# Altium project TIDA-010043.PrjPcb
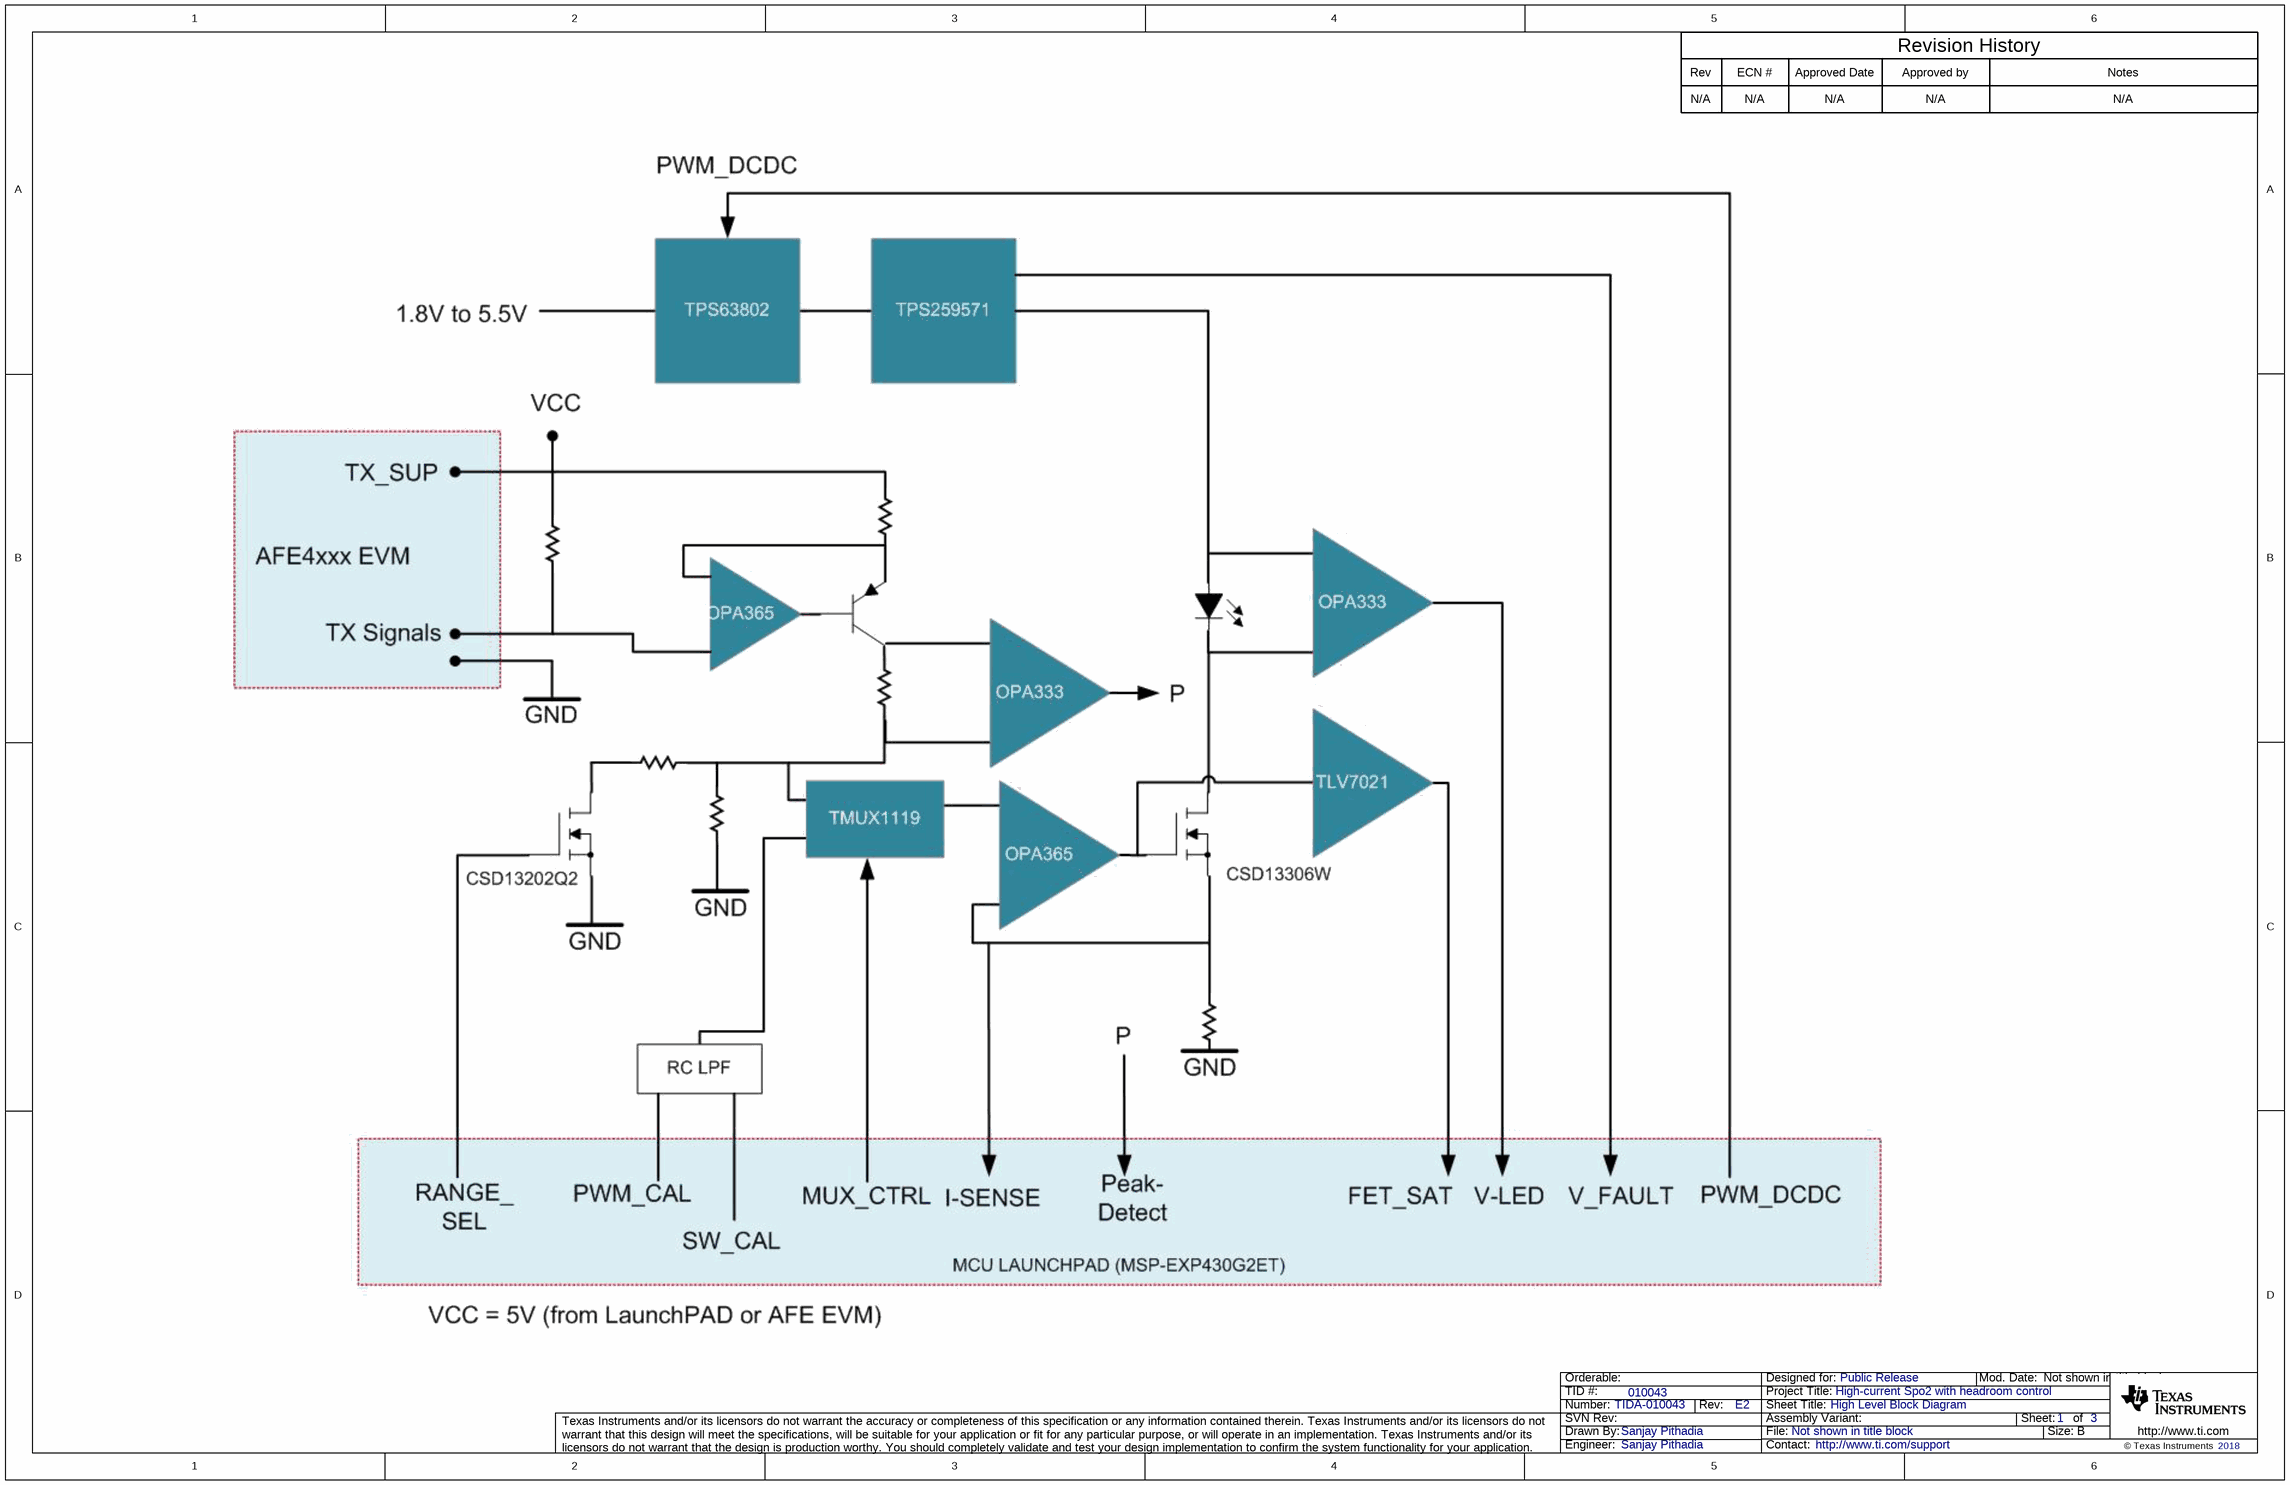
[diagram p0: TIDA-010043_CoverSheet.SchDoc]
CopyrightYear: 2018; PCB_Layout: TESSOLVE; PCB_Rev: E2; PRJ_Customer: Public Release; PRJ_Engineer: Sanjay Pithadia; PRJ_Number: TIDA-010043; PRJ_Title: High-current Spo2 with headroom control; SCH_Rev: E2; TechSupport: http://www.ti.com/support; TID: 010043
3 sheets, 122 parts. Net scope: global (net labels, ports and power ports of the same name join across sheets).
Board file: TIDA-010043_PCB.PcbDoc
Sheets:
  TIDA-010043_CoverSheet.SchDoc
  TIDA-010043_Main.SchDoc
  TIDA-010043_EVM_Hardware.SchDoc

## Sheet TIDA-010043_CoverSheet.SchDoc: High Level Block Diagram
size 431 x 279 mm; Date: Not shown in title block; ApprovedBy: Not shown in title block; CheckedBy: Not shown in title block; Author: Not shown in title block; CompanyName: Not shown in title block; DrawnBy: Sanjay Pithadia; Engineer: Sanjay Pithadia; Organization: Not shown in title block; Address1: Not shown in title block; Address2: Not shown in title block; Address3: Not shown in title block; Address4: Not shown in title block; DocumentNumber: 1; Revision: Use project parameter SCH_Rev; SheetNumber: 1; SheetTotal: 3; PageSetup: Record=PageOptions¦CenterHorizontal=True¦CenterVertical=True¦PrintScale=1.00¦XCorrection=1.00¦YCorrection=1.00¦PrintKind=0¦BorderSize=5000000¦LeftOffset=0¦BottomOffset=0¦Orientation=2¦PaperLength=1000¦PaperWidth=1000¦Scale=100¦PaperSource=15¦PrintQuality=600¦MediaType=1¦DitherType=10¦PaperKind=Letter¦PrintScaleMode=1

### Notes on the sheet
- Rev
- N/A
- ECN #
- Approved Date
- Approved by
- Revision History
- Notes

## Sheet TIDA-010043_Main.SchDoc: Main
size 431 x 279 mm; Date: Not shown in title block; ApprovedBy: Not shown in title block; CheckedBy: Not shown in title block; Author: Not shown in title block; CompanyName: Not shown in title block; DrawnBy: Sanjay Pithadia; Engineer: Sanjay Pithadia; Organization: Not shown in title block; Address1: Not shown in title block; Address2: Not shown in title block; Address3: Not shown in title block; Address4: Not shown in title block; DocumentNumber: 1; Revision: Use project parameter SCH_Rev; SheetNumber: 2; SheetTotal: 3; PageSetup: Record=PageOptions¦CenterHorizontal=True¦CenterVertical=True¦PrintScale=1.00¦XCorrection=1.00¦YCorrection=1.00¦PrintKind=0¦BorderSize=5000000¦LeftOffset=0¦BottomOffset=0¦Orientation=2¦PaperLength=1000¦PaperWidth=1000¦Scale=100¦PaperSource=15¦PrintQuality=600¦MediaType=1¦DitherType=10¦PaperKind=Letter¦PrintScaleMode=1
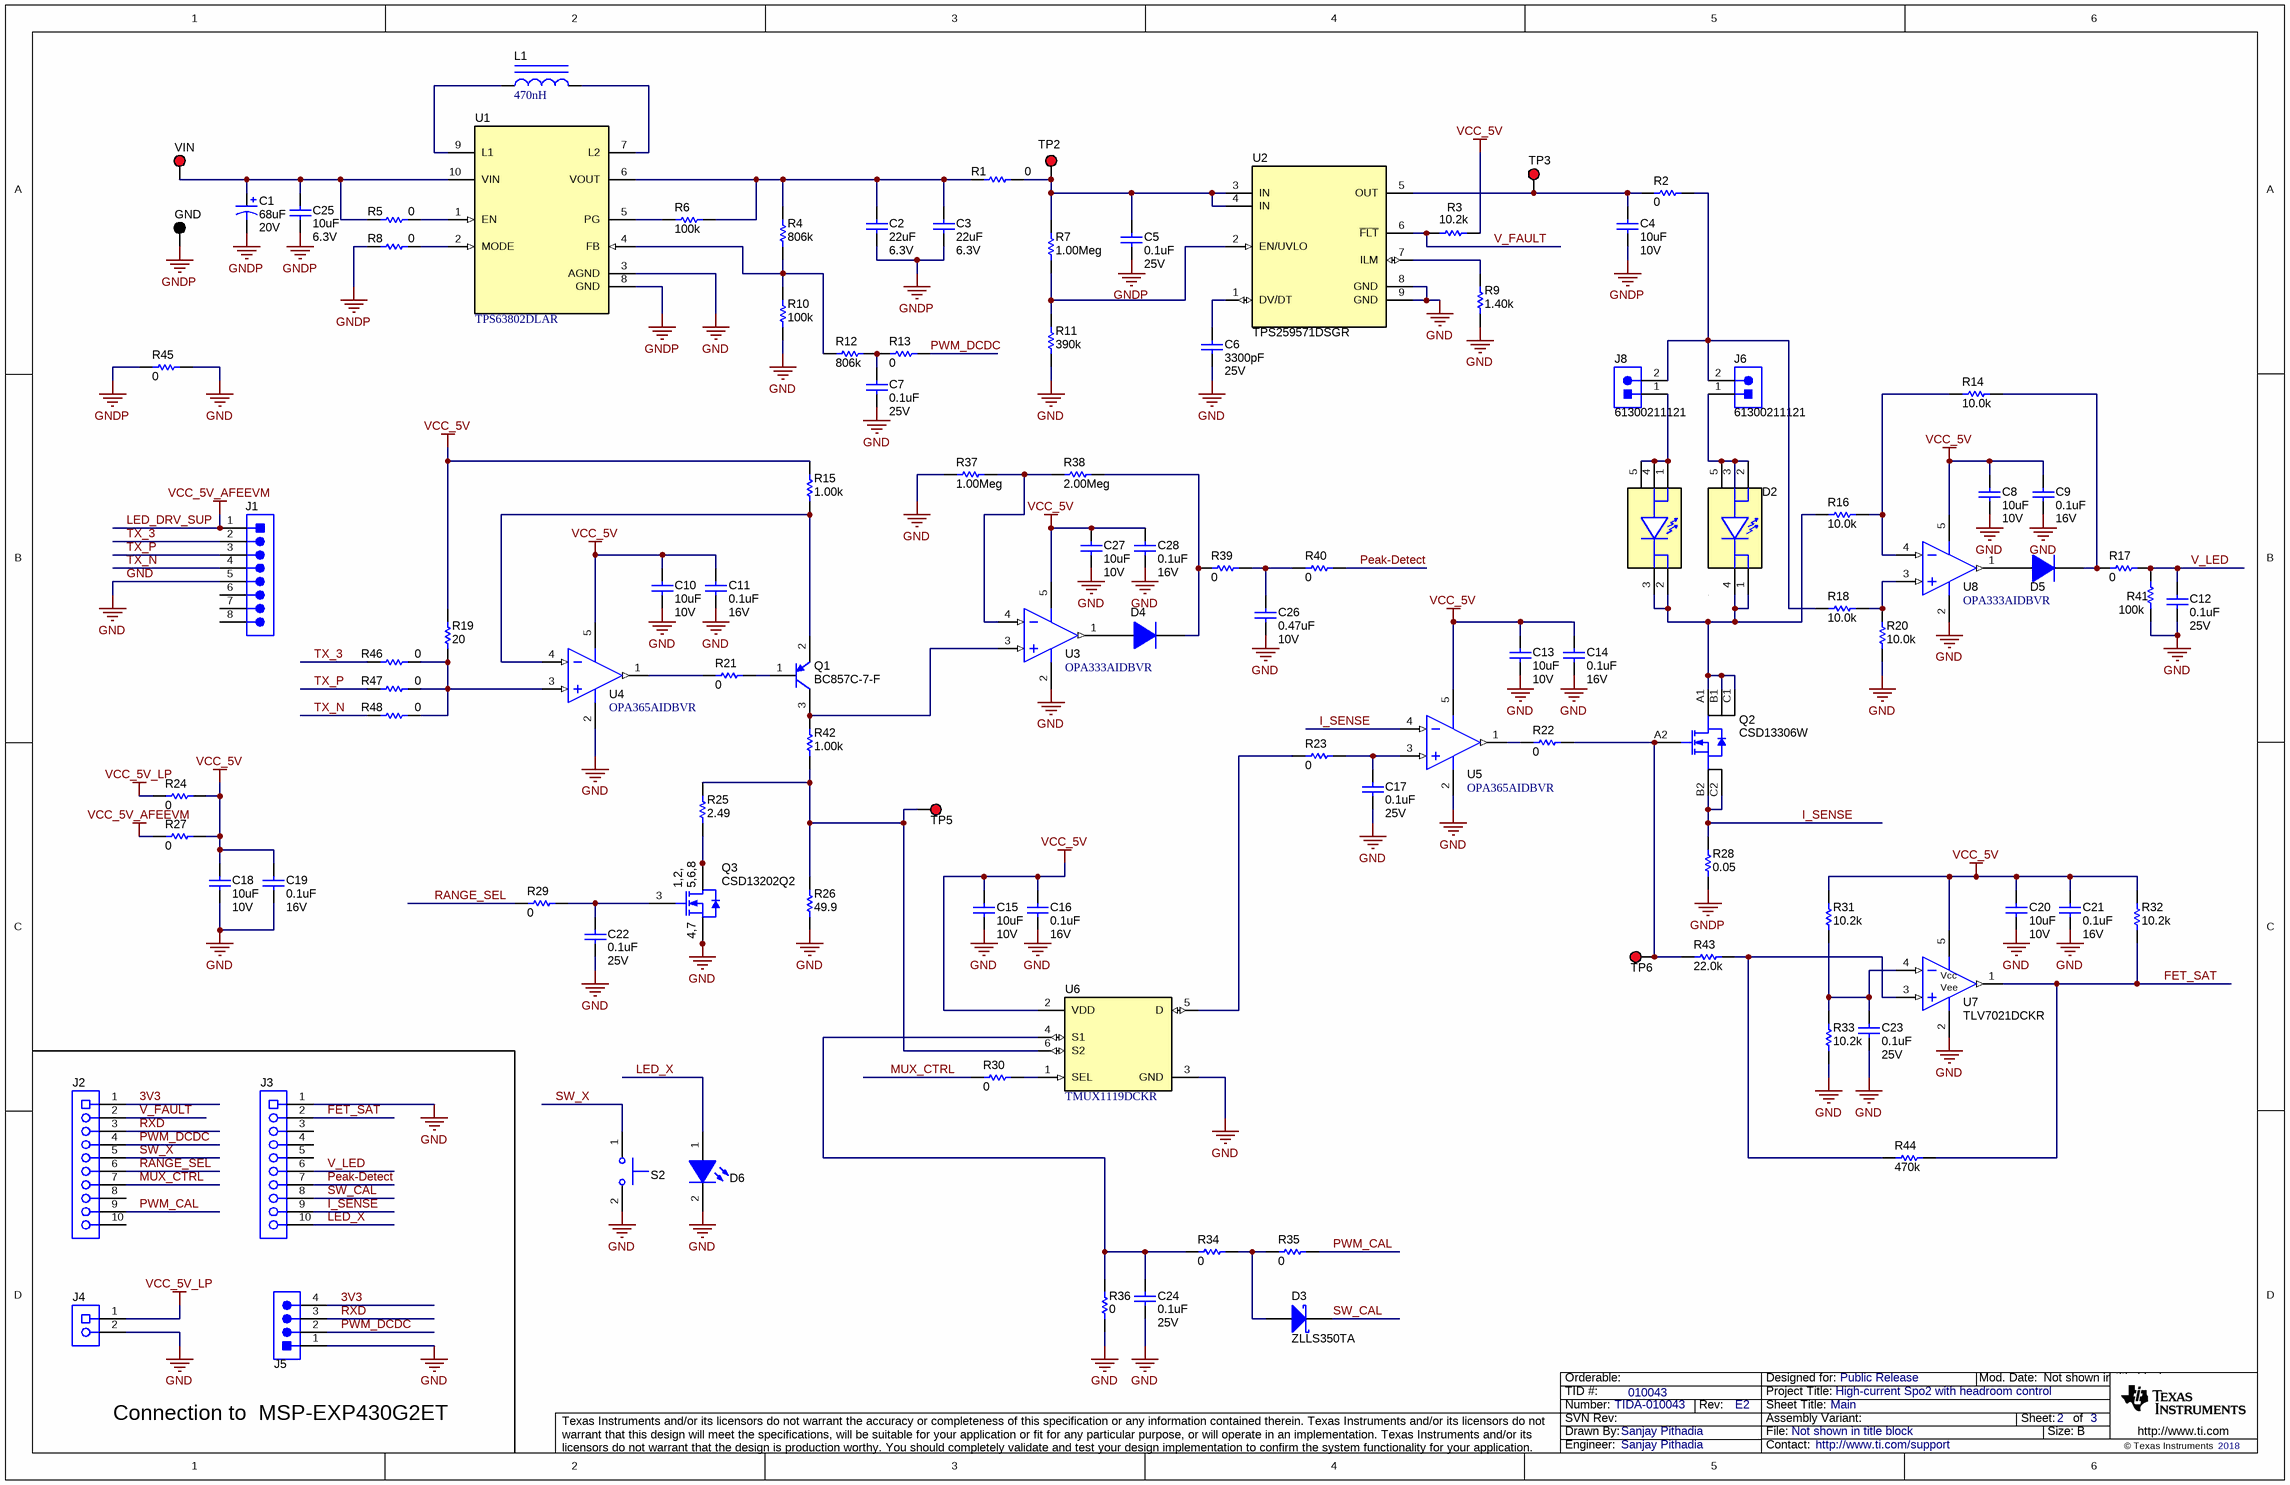
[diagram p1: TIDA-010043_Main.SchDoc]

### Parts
C1  value 68uF  Value2: 20V  [7343-31]  (hidden comment: T495D686K020ATE150)
C2  value 22uF  Value2: 6.3V  [0603]  (hidden comment: GRM188R60J226MEA0D)
C3  value 22uF  Value2: 6.3V  [0603]  (hidden comment: GRM188R60J226MEA0D)
C4  value 10uF  Value2: 10V  [0603]  (hidden comment: GRM188Z71A106MA73D)
C5  value 0.1uF  Value2: 25V  [0603]  (hidden comment: 06033C104KAT2A)
C6  value 3300pF  Value2: 25V  [0603]  (hidden comment: GRM188R71E332KA01D)
C7  value 0.1uF  Value2: 25V  [0603]  (hidden comment: 06033C104KAT2A)
C8  value 10uF  Value2: 10V  [0805_HV]  (hidden comment: 885012207026)
C9  value 0.1uF  Value2: 16V  [0402]  (hidden comment: 885012205037)
C10  value 10uF  Value2: 10V  [0805_HV]  (hidden comment: 885012207026)
C11  value 0.1uF  Value2: 16V  [0402]  (hidden comment: 885012205037)
C12  value 0.1uF  Value2: 25V  [0603]  (hidden comment: 06033C104KAT2A)
C13  value 10uF  Value2: 10V  [0805_HV]  (hidden comment: 885012207026)
C14  value 0.1uF  Value2: 16V  [0402]  (hidden comment: 885012205037)
C15  value 10uF  Value2: 10V  [0805_HV]  (hidden comment: 885012207026)
C16  value 0.1uF  Value2: 16V  [0402]  (hidden comment: 885012205037)
C17  value 0.1uF  Value2: 25V  [0603]  (hidden comment: 06033C104KAT2A)
C18  value 10uF  Value2: 10V  [0805_HV]  (hidden comment: 885012207026)
C19  value 0.1uF  Value2: 16V  [0402]  (hidden comment: 885012205037)
C20  value 10uF  Value2: 10V  [0805_HV]  (hidden comment: 885012207026)
C21  value 0.1uF  Value2: 16V  [0402]  (hidden comment: 885012205037)
C22  value 0.1uF  Value2: 25V  [0603]  (hidden comment: 06033C104KAT2A)
C23  value 0.1uF  Value2: 25V  [0603]  (hidden comment: 06033C104KAT2A)
C24  value 0.1uF  Value2: 25V  [0603]  (hidden comment: 06033C104KAT2A)
C25  value 10uF  Value2: 6.3V  [0603]  (hidden comment: GRM188R60J106ME84)
C26  value 0.47uF  Value2: 10V  [0603]  (hidden comment: GRM188R71A474KA61D)
C27  value 10uF  Value2: 10V  [0805_HV]  (hidden comment: 885012207026)
C28  value 0.1uF  Value2: 16V  [0402]  (hidden comment: 885012205037)
D1  LZ1-00G102-0000  [LED_LZ1_Green]  (value not drawn)
D2  LZ1-00R102-0000  [LED_LZ1_Red]  (value not drawn)
D3  ZLLS350TA  [SOD-523]
D4  1N4148W-7-F  [SOD-123]  (value not drawn)
D5  1N4148W-7-F  [SOD-123]  (value not drawn)
D6  SM0603GCL  [SM0603GCL_GREEN]  (value not drawn)
GND  5001  [Keystone5001]  (value not drawn)
J1  850-10-008-20-001000  [Mill-Max_850-10-008-20-001000]  (value not drawn)
J2  61301011821  [Wurth_61301011821]  (value not drawn)
J3  61301011821  [Wurth_61301011821]  (value not drawn)
J4  PPTC021LFBN-RC  [CONN_PPTC021LFBN-RC]  (value not drawn)
J5  61000418221  [Wurth_61000418221]  (value not drawn)
J6  61300211121  [WURTH_61300211121]
J8  61300211121  [WURTH_61300211121]
L1  ValueDisplayed: 470nH  [DFE201612E]  (hidden comment: DFE201612E-R47M=P2)
Q1  BC857C-7-F  [SOT-23]
Q2  CSD13306W  [YZC0006ABAB]
Q3  CSD13202Q2  [DQK0006C]
R1  value 0  [5106]  (hidden comment: 5106)
R2  value 0  [5106]  (hidden comment: 5106)
R3  value 10.2k  [0603]  (hidden comment: RC0603FR-0710K2L)
R4  value 806k  [0603]  (hidden comment: RC0603FR-07806KL)
R5  value 0  [0603]  (hidden comment: RMCF0603ZT0R00)
R6  value 100k  [0603]  (hidden comment: CRCW0603100KFKEA)
R7  value 1.00Meg  [0603]  (hidden comment: RC0603FR-071ML)
R8  value 0  [0603]  (hidden comment: RMCF0603ZT0R00)
R9  value 1.40k  [0603]  (hidden comment: RC0603FR-071K4L)
R10  value 100k  [0603]  (hidden comment: CRCW0603100KFKEA)
R11  value 390k  [0603]  (hidden comment: RC0603FR-07390KL)
R12  value 806k  [0603]  (hidden comment: RC0603FR-07806KL)
R13  value 0  [0603]  (hidden comment: RMCF0603ZT0R00)
R14  value 10.0k  [0603]  (hidden comment: RMCF0603FT10K0)
R15  value 1.00k  [0603]  (hidden comment: ERJ-3EKF1001V)
R16  value 10.0k  [0603]  (hidden comment: RMCF0603FT10K0)
R17  value 0  [0603]  (hidden comment: RMCF0603ZT0R00)
R18  value 10.0k  [0603]  (hidden comment: RMCF0603FT10K0)
R19  Res_ohm: 20  [1206]  (hidden comment: CRCW120620R0FKEAHP)
R20  value 10.0k  [0603]  (hidden comment: RMCF0603FT10K0)
R21  value 0  [0603]  (hidden comment: RMCF0603ZT0R00)
R22  value 0  [0603]  (hidden comment: RMCF0603ZT0R00)
R23  value 0  [0603]  (hidden comment: RMCF0603ZT0R00)
R24  value 0  [0603]  (hidden comment: RMCF0603ZT0R00)
R25  value 2.49  [0603]  (hidden comment: CRCW06032R49FKEA)
R26  value 49.9  [0603]  (hidden comment: CRCW060349R9FKEA)
R27  value 0  [0603]  (hidden comment: RMCF0603ZT0R00)
R28  value 0.05  [1206]  (hidden comment: CRM1206-FZ-R050ELF)
R29  value 0  [0603]  (hidden comment: RMCF0603ZT0R00)
R30  value 0  [0603]  (hidden comment: RMCF0603ZT0R00)
R31  value 10.2k  [0603]  (hidden comment: RC0603FR-0710K2L)
R32  value 10.2k  [0603]  (hidden comment: RC0603FR-0710K2L)
R33  value 10.2k  [0603]  (hidden comment: RC0603FR-0710K2L)
R34  value 0  [0603]  (hidden comment: RMCF0603ZT0R00)
R35  value 0  [0603]  (hidden comment: RMCF0603ZT0R00)
R36  value 0  [0603]  (hidden comment: RMCF0603ZT0R00)
R37  value 1.00Meg  [0603]  (hidden comment: RC0603FR-071ML)
R38  value 2.00Meg  [0603]  (hidden comment: RC0603FR-072ML)
R39  value 0  [0603]  (hidden comment: RMCF0603ZT0R00)
R40  value 0  [0603]  (hidden comment: RMCF0603ZT0R00)
R41  value 100k  [0603]  (hidden comment: RC0603FR-07100KL)
R42  value 1.00k  [0603]  (hidden comment: ERJ-3EKF1001V)
R43  value 22.0k  [0603]  (hidden comment: ERJ-3EKF2202V)
R44  value 470k  [0603]  (hidden comment: RC0603FR-07470KL)
R45  value 0  [0603]  (hidden comment: RMCF0603ZT0R00)
R46  value 0  [0603]  (hidden comment: RMCF0603ZT0R00)
R47  value 0  [0603]  (hidden comment: RMCF0603ZT0R00)
R48  value 0  [0603]  (hidden comment: RMCF0603ZT0R00)
S2  SKRKAEE010  [SW_SKRKAEE010]  (value not drawn)
TP2  5000  [Keystone5000]  (value not drawn)
TP3  5000  [Keystone5000]  (value not drawn)
TP5  5000  [Keystone5000]  (value not drawn)
TP6  5000  [Keystone5000]  (value not drawn)
U1  TPS63802DLAR  [DLA0010A]
U2  TPS259571DSGR  [DSG0008A]
U3  OPA333AIDBVR  [DBV0005A_N]
U4  OPA365AIDBVR  [DBV0005A_N]
U5  OPA365AIDBVR  [DBV0005A_N]
U6  TMUX1119DCKR  [DCK0006A_N]  (no BOM)
U7  TLV7021DCKR  [DCK0005A_L]
U8  OPA333AIDBVR  [DBV0005A_N]
VIN  5000  [Keystone5000]  (value not drawn)

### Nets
GND: C6.2 C7.2 C8.2 C9.2 C10.2 C11.2 C12.2 C13.2 C14.2 C15.2 C16.2 C17.2 C18.2 C19.2 C20.2 C21.2 C22.2 C23.2 C24.2 C26.2 C27.2 C28.2 D6.2(K) J1.5 J3.1 J4.2 J5.1 Q3.4(S) Q3.7(S) R9.1 R10.2 R11.1 R20.1 R26.1 R33.1 R36.1 R37.1 R41.1 R45.2 S2.2 U1.3(AGND) U2.8(GND) U2.9(GND) U3.2(V-) U4.2(V-) U5.2(V-) U6.3(GND) U7.2(VEE) U8.2(V-)
GNDP: C1.2(-) C2.2 C3.2 C4.2 C5.2 C25.2 GND.1 R8.1 R28.1 R45.1 U1.8(GND)
LED_DRV_SUP: J1.1 R27.1  [also labelled VCC_5V_AFEEVM]
VCC_5V: C8.1 C9.1 C10.1 C11.1 C13.1 C14.1 C15.1 C16.1 C18.1 C19.1 C20.1 C21.1 C27.1 C28.1 R3.2 R15.2 R19.2 R24.2 R27.2 R31.2 R32.2 U3.5(V+) U4.5(V+) U5.5(V+) U6.2(VDD) U7.5(VCC) U8.5(V+)
VCC_5V_LP: J4.1 R24.1
3V3: J2.1 J5.4
FET_SAT: J3.2 R32.1 R44.2 U7.1(OUT)
I_SENSE: J3.9 Q2.B2(S) Q2.C2(S) R28.2 U5.4(IN-)
LED_X: D6.1(A) J3.10
MUX_CTRL: J2.7 R30.1
Peak-Detect: J3.7 R40.2
PWM_CAL: J2.9 R35.2
PWM_DCDC: J2.4 J5.2 R13.2
RANGE_SEL: J2.6 R29.1
RXD: J2.3 J5.3
SW_CAL: D3.1(K) J3.8
SW_X: J2.5 S2.1
TX_3: J1.2 R46.1
TX_N: J1.4 R48.1
TX_P: J1.3 R47.1
V_FAULT: J2.2 R3.1 U2.6(~{FLT})
V_LED: C12.1 J3.6 R17.2 R41.2
NetC1_1: C1.1(+) C25.1 R5.1 U1.10(VIN) VIN.1
NetC2_1: C2.1 C3.1 R1.1 R4.2 R6.1 U1.6(VOUT)
NetC4_1: C4.1 R2.1 TP3.1 U2.5(OUT)
NetC5_1: C5.1 R1.2 R7.2 TP2.1 U2.3(IN) U2.4(IN)
NetC6_1: C6.1 U2.1(DV/DT)
NetC7_1: C7.1 R12.1 R13.1
NetC17_1: C17.1 R23.2 U5.3(IN+)
NetC22_1: C22.1 Q3.3(G) R29.2
NetC23_1: C23.1 R31.1 R33.2 U7.4(IN-)
NetC24_1: C24.1 R34.1 R36.2 U6.4(S1)
NetC26_1: C26.1 R39.2 R40.1
NetD1_1: D1.1(A) D1.4(A) D1.5(EP) J8.1
NetD1_2: D1.2(K) D1.3(K) D2.1(K) D2.4(K) Q2.A1(D) Q2.B1(D) Q2.C1(D) R16.1
NetD2_2: D2.2(A) D2.3(A) D2.5(EP) J6.1
NetD3_2: D3.2(A) R34.2 R35.1
NetD4_1: D4.1(K) R38.2 R39.1
NetD4_2: D4.2(A) U3.1(OUT)
NetD5_1: D5.1(K) R14.2 R17.1
NetD5_2: D5.2(A) U8.1(OUT)
NetJ6_2: J6.2 J8.2 R2.2 R18.1
NetL1_1: L1.1 U1.9(L1)
NetL1_2: L1.2 U1.7(L2)
NetQ1_1: Q1.1(B) R21.2
NetQ1_2: Q1.2(E) R15.1 U4.4(IN-)
NetQ1_3: Q1.3(C) R42.2 U3.3(IN+)
NetQ2_A2: Q2.A2(G) R22.2 R43.1 TP6.1
NetQ3_1: Q3.1(D) Q3.2(D) Q3.5(D) Q3.6(D) Q3.8(D) R25.1
NetR4_1: R4.1 R10.1 R12.2 U1.4(FB)
NetR5_2: R5.2 U1.1(EN)
NetR6_2: R6.2 U1.5(PG)
NetR7_1: R7.1 R11.2 U2.2(EN/UVLO)
NetR8_2: R8.2 U1.2(MODE)
NetR9_2: R9.2 U2.7(ILM)
NetR14_1: R14.1 R16.2 U8.4(IN-)
NetR18_2: R18.2 R20.2 U8.3(IN+)
NetR19_1: R19.1 R46.2 R47.2 R48.2 U4.3(IN+)
NetR21_1: R21.1 U4.1(VOUT)
NetR22_1: R22.1 U5.1(VOUT)
NetR23_1: R23.1 U6.5(D)
NetR25_2: R25.2 R26.2 R42.1 TP5.1 U6.6(S2)
NetR30_2: R30.2 U6.1(SEL)
NetR37_2: R37.2 R38.1 U3.4(IN-)
NetR43_2: R43.2 R44.1 U7.3(IN+)

Not connected (* = marked no-connect by the designer): J1 6 7 8; J2 8 10; J3 3 4 5

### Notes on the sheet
- Connection to  MSP-EXP430G2ET

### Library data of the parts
C1 = CMP-0011790-2: CAP, TA, 68 uF, 20 V, +/- 10%, 0.15 ohm, SMD; Manufacturer: Kemet; TaMin_C: -55°C; ESR_ohm: 1.5d; Polarized: Y; SizeAreaWB_mm2: 58.59; U/M: EA; TaMax_C: 125°C; SizeZ_mm: 3.1; SizeX_mm: 7.3; SizeY_mm: 4.3; Cap_Case: D; SizeArea_mm2: 31.39; CompType: Capacitor; Cap_F: 68µF; IRMS_A: 9dA; AEC Category: Q200
C2 C3 = CMP-0007306-5: CAP, CERM, 22 uF, 6.3 V, +/- 20%, X5R, 0603; Manufacturer: MuRata; TaMin_C: -55°C; Polarized: N; SizeAreaWB_mm2: 4.68; Value1: Unknown; U/M: EA; TaMax_C: 85°C; SizeZ_mm: 1; SizeX_mm: 1.6; SizeY_mm: 0.8; SizeArea_mm2: 1.28; CompType: Capacitor; Cap_F: 22µF; AEC Category: Q200
C4 = CMP-0007497-5: CAP, CERM, 10 uF, 10 V, +/- 20%, X7R, 0603; Manufacturer: MuRata; TaMin_C: -55°C; Polarized: N; SizeAreaWB_mm2: 4.68; Value1: Unknown; U/M: EA; TaMax_C: 125°C; SizeZ_mm: 1; SizeX_mm: 1.6; SizeY_mm: 0.8; SizeArea_mm2: 1.28; CompType: Capacitor; Cap_F: 10µF; AEC Category: Q200
C5 C7 C12 C17 C22-C24 = CMP-0006753-4: CAP, CERM, 0.1 uF, 25 V, +/- 10%, X7R, 0603; Manufacturer: AVX; TaMin_C: -55°C; ESR_ohm: 0.05; Polarized: N; SizeAreaWB_mm2: 4.68; Value1: 0.05 ohm; U/M: EA; TaMax_C: 125°C; SizeZ_mm: 1; SizeX_mm: 1.6; SizeY_mm: 0.8; SizeArea_mm2: 1.28; CompType: Capacitor; Cap_F: 100nF; AEC Category: Q200
C6 = CMP-0007418-4: CAP, CERM, 3300 pF, 25 V, +/- 10%, X7R, 0603; Manufacturer: MuRata; TaMin_C: -55°C; Polarized: N; SizeAreaWB_mm2: 4.68; Value1: Unknown; U/M: EA; TaMax_C: 125°C; SizeZ_mm: 1; SizeX_mm: 1.6; SizeY_mm: 0.8; SizeArea_mm2: 1.28; CompType: Capacitor; Cap_F: 3.3nF; AEC Category: Q200
C8 C10 C13 C15 C18 C20 C27 = CMP-0007691-2: CAP, CERM, 10 uF, 10 V, +/- 10%, X7R, 0805; Manufacturer: Wurth Elektronik; TaMin_C: -55°C; Polarized: N; SizeAreaWB_mm2: 6.75; Value1: Unknown; U/M: EA; TaMax_C: 125°C; SizeZ_mm: 1.45; SizeX_mm: 2; SizeY_mm: 1.25; Cap_Case: 0805; SizeArea_mm2: 2.5; CompType: Capacitor; Cap_F: 10µF; AEC Category: Q200
C9 C11 C14 C16 C19 C21 C28 = CMP-0006228-2: CAP, CERM, 0.1 uF, 16 V, +/- 10%, X7R, 0402; Manufacturer: Wurth Elektronik; TaMin_C: -55°C; Polarized: N; SizeAreaWB_mm2: 3; Value1: Unknown; U/M: EA; TaMax_C: 125°C; SizeZ_mm: 0.6; SizeX_mm: 1; SizeY_mm: 0.5; CompType: Capacitor; Cap_F: 100nF; AEC Category: Q200
C25 = CMP-0007304-5: CAP, CERM, 10 uF, 6.3 V, +/- 20%, X5R, 0603; Manufacturer: MuRata; TaMin_C: -55°C; Polarized: N; SizeAreaWB_mm2: 4.68; Value1: Unknown; U/M: EA; TaMax_C: 85°C; SizeZ_mm: 1; SizeX_mm: 1.6; SizeY_mm: 0.8; SizeArea_mm2: 1.28; CompType: Capacitor; Cap_F: 10µF; AEC Category: Q200
C26 = CMP-0007373-4: CAP, CERM, 0.47 uF, 10 V, +/- 10%, X7R, 0603; Manufacturer: MuRata; TaMin_C: -55°C; Polarized: N; SizeAreaWB_mm2: 4.68; Value1: Unknown; U/M: EA; TaMax_C: 125°C; SizeZ_mm: 1; SizeX_mm: 1.6; SizeY_mm: 0.8; SizeArea_mm2: 1.28; CompType: Capacitor; Cap_F: 470nF; AEC Category: Q200
D1 = CMP-0085613-1: LED, Green, SMD; Manufacturer: LEDEngin; Value1: W; Vf_V: 3.95V; SizeY_mm: 4.4; SizeZ_mm: 2.6; Io_A: 1.5A; Angle: 100; SizeArea_mm2: 19.36; Tjmax_C: 150°C; SizeAreaWB_mm2: 29.16
D2 = CMP-0085612-1: LED, Red, SMD; Manufacturer: LEDEngin; Io_A: 1.5A; Tjmax_C: 125°C; Vf_V: 3V; SizeArea_mm2: 19.36; Angle: 100; SizeY_mm: 4.4; Value1: W; SizeAreaWB_mm2: 29.16; SizeZ_mm: 2.6
D3 = CMP-0028378-3: Diode, Schottky, 40 V, 0.38 A, SOD-523; Manufacturer: Diodes Inc.; Value1: 0.38A; Value2: 0.79V; Green_Lifecycle: Active; SizeArea_mm2: 1.53; Vf_V: 790mV; AEC Category: Q101; SizeZ_mm: 0.65; Io_A: 380mA; SizeY_mm: 0.9; SizeAreaWB_mm2: 5.13; Green_REACh: Passed; SizeX_mm: 1.7; Vr_V: 40V; Value: 40V
D4 D5 = CMP-0029001-2: Diode, Ultrafast, 100 V, 0.15 A, SOD-123; Manufacturer: Diodes Inc.; SizeX_mm: 3.85; Value2: 1.25V; Green_REACh: Passed; TJmax_C: 150°C; AEC Category: Q101; SizeAreaWB_mm2: 13.095; Value: 100V; Green_Lifecycle: Active; SizeY_mm: 1.7; Value1: 0.15A; SizeArea_mm2: 6.545; Io_A: 150mA; SizeZ_mm: 1.35
D6 = CMP-0002869-2: LED, Green, SMD; Manufacturer: Bivar; Value2: 1.9V; Tjmax_C: 80°C; Type: AlInGaP; Value1: W; Io_A: 2mA
GND = CMP-0055138-1: Test Point, Miniature, Black, TH; Manufacturer: Keystone; CNHeader: FALSE; Green_Lifecycle: Active; Green_REACh: Passed; ContactFinish: Silver; CT: TRUE
J1 = CMP-0055014-1: Header, 50mil, 8x1, R/A, TH; Manufacturer: Mill-Max; CT: FALSE
J2 J3 = CMP-0054762-1: Receptacle, 2.54mm, 10x1, Gold, TH; Manufacturer: Wurth Elektronik; CNHeader: FALSE; Current_A: 3A; Gender: Female; Cert_CSA: Y; Voltage_V: 250V; Row_Count: 1; Pitch_mm: 2.54
J4 = CMP-0054631-1: Receptacle, 100mil, 2x1, Tin, TH; Manufacturer: Sullins Connector Solutions; CNHeader: FALSE; Current_A: 3A; Gender: Female; Voltage_V: 250V; CompType: Socket Strip; Pitch_mm: 2.54; CT: TRUE; Cert_UL: Y
J5 = CMP-0054788-1: Header, 2.54mm, 4x1, Gold, SMT; Manufacturer: Wurth Elektronik; CNHeader: TRUE; Shrouded: N; Gender: Male; Row_Count: 1; Pitch_mm: 2.54; CT: FALSE
J6 J8 = CMP-0054794-1: Header, 2.54 mm, 2x1, Gold, TH; Manufacturer: Wurth Elektronik; CNHeader: TRUE; Green_Lifecycle: Active; Green_REACh: Passed; CT: FALSE
L1 = CMP-0080779-1: Inductor, Shielded, Metal Composite, 470 nH, 4.5 A, 0.026 ohm, SMD; Manufacturer: MuRata; Isat: 5.5A @ 30% inductance drop; Irms: 4.5A @ 40C rise; SizeAreaWB_mm2: 7.8; DCR_ohm: 0.026; Value: 470nH; Imax_A: 4.5A; SizeZ_mm: 1.2; SizeX_mm: 2; SizeY_mm: 1.6; SizeArea_mm2: 3.2; AEC Qualified: N; AEC Category: Q200
Q1 = CMP-0000316-2: Transistor, PNP, 45 V, 0.1 A, SOT-23; Manufacturer: Diodes Inc.; TaMax_C: 150°C; Value2: 600; Value1: 0.1 A; Vcesat1_V: 75mV; SizeX_mm: 2.5; SizeY_mm: 3; TaMin_C: -65°C; IcRated_A: 1dA; CompType: BJT; SizeZ_mm: 1.1; Value: 45 V; SizeArea_mm2: 7.5; NPN: 0; Vceo_V: 45V; PNP: 1; AEC Category: Q101; SizeAreaWB_mm2: 14; U/M: EA
Q2 = CMP-0000196-1: MOSFET, N-CH, 12 V, 3.5 A, YZC0006ABAB (DSBGA-6); Alternate Manufacturer: None; Manufacturer: Texas Instruments; SizeZ_mm: 1; ChType: N; Value2: 8.6 nC; Value1: 0.01; VdsMax_V: 12V; SizeX_mm: 1.25; SizeAreaWB_mm2: 6.1875; SizeY_mm: 1.75; Vgs_V: 10V; QgTyp_nC: 8.6; Value: 12V; Rdson45_ohm: 0.0102; SizeArea_mm2: 2.1875; AEC Category: Q101; IdsMax_A: 3.5A; U/M: EA
Q3 = CMP-0000193-1: MOSFET, N-CH, 12 V, 22 A, DQK0006C (WSON-6); Alternate Manufacturer: None; Manufacturer: Texas Instruments; SizeZ_mm: 0.8; ChType: N; Value2: 5.1 nC; Value1: 0.009; VdsMax_V: 12V; SizeX_mm: 2; Vgs_V: 8V; Value: 12V; Rdson45_ohm: 9.3m; SizeArea_mm2: 4; AEC Category: Q101; IdsMax_A: 22A; SizeAreaWB_mm2: 9; U/M: EA; QgTyp_nC: 5.1
R1 R2 = CMP-0020833-2: RES, 0, 1%, 0.5 W, 0805; Manufacturer: Keystone; Power_W: 500mW; TempCo: ppm/C; U/M: EA; SizeX_mm: 2; SizeY_mm: 1.25; SizeZ_mm: 0.84; Value2: 0.5W; SizeArea_mm2: 2.5; CompType: Resistor; AEC Qualified: N; AEC Category: Q200
R3 R31-R33 = CMP-0022743-5: RES, 10.2 k, 1%, 0.1 W, 0603; Manufacturer: Yageo; Power_W: 100mW; TempCo: 100 ppm/C; Value_Code: 10k2; EIA_Code: E96; SizeX_mm: 1.6; SizeY_mm: 0.8; SizeZ_mm: 1; Value2: 0.1W; SizeArea_mm2: 1.28; CompType: Resistor; AEC Qualified: N; VDC_V: 75V; AEC Category: Q200; SizeAreaWB_mm2: 4.68
R4 R12 = CMP-0023283-4: RES, 806 k, 1%, 0.1 W, 0603; Manufacturer: Yageo; Power_W: 100mW; TempCo: 100 ppm/C; EIA_Code: E96; SizeX_mm: 1.6; SizeY_mm: 0.8; SizeZ_mm: 1; Value2: 0.1W; SizeArea_mm2: 1.28; CompType: Resistor; AEC Qualified: N; VDC_V: 75V; AEC Category: Q200; SizeAreaWB_mm2: 4.68
R5 R8 R13 R17 R21-R24 R27 R29 R30 R34-R36 R39 R40 R45-R48 = CMP-0023343-3: RES, 0, 1%, 0.1 W, AEC-Q200 Grade 0, 0603; Manufacturer: Stackpole Electronics Inc; Power_W: 100mW; TempCo: ppm/C; U/M: EA; SizeX_mm: 1.6; SizeY_mm: 0.8; SizeZ_mm: 1; Value2: 0.1W; SizeArea_mm2: 1.28; CompType: Resistor; AEC Qualified: Y; AEC Category: Q200
R6 R10 = CMP-0021990-4: RES, 100 k, 1%, 0.1 W, AEC-Q200 Grade 0, 0603; Manufacturer: Vishay-Dale; Power_W: 100mW; TempCo: 100 ppm/C; EIA_Code: E96; SizeX_mm: 1.6; SizeY_mm: 0.8; SizeZ_mm: 1; Value2: 0.1W; SizeArea_mm2: 1.28; CompType: Resistor; AEC Qualified: Y; VDC_V: 75V; AEC Category: Q200; AEC Grade: 0
R7 R37 = CMP-0022899-4: RES, 1.00 M, 1%, 0.1 W, 0603; Manufacturer: Yageo; Power_W: 100mW; TempCo: 100 ppm/C; Value_Code: 1M00; EIA_Code: E96; Res_ohm: 1M; SizeX_mm: 1.6; SizeY_mm: 0.8; SizeZ_mm: 1; Value2: 0.1W; SizeArea_mm2: 1.28; CompType: Resistor; AEC Qualified: N; VDC_V: 75V; AEC Category: Q200; ValueDisplayed: 1.00M; SizeAreaWB_mm2: 4.68
R9 = CMP-0022880-5: RES, 1.40 k, 1%, 0.1 W, 0603; Manufacturer: Yageo; Power_W: 100mW; TempCo: 100 ppm/C; Value_Code: 1k40; EIA_Code: E96; Res_ohm: 1.4k; SizeX_mm: 1.6; SizeY_mm: 0.8; SizeZ_mm: 1; Value2: 0.1W; SizeArea_mm2: 1.28; CompType: Resistor; AEC Qualified: N; VDC_V: 75V; AEC Category: Q200; SizeAreaWB_mm2: 4.68
R11 = CMP-0023068-4: RES, 390 k, 1%, 0.1 W, 0603; Manufacturer: Yageo; Power_W: 100mW; TempCo: 100 ppm/C; SizeX_mm: 1.6; SizeY_mm: 0.8; SizeZ_mm: 1; Value2: 0.1W; SizeArea_mm2: 1.28; CompType: Resistor; AEC Qualified: N; VDC_V: 75V; AEC Category: Q200; SizeAreaWB_mm2: 4.68
R14 R16 R18 R20 = CMP-0023341-3: RES, 10.0 k, 1%, 0.1 W, AEC-Q200 Grade 0, 0603; Manufacturer: Stackpole Electronics Inc; Power_W: 100mW; TempCo: 100 ppm/C; Value_Code: 10k0; U/M: EA; EIA_Code: E96; Res_ohm: 10k; SizeX_mm: 1.6; SizeY_mm: 0.8; SizeZ_mm: 1; Value2: 0.1W; SizeArea_mm2: 1.28; CompType: Resistor; AEC Qualified: Y; VDC_V: 75V; AEC Grade: 0; AEC Category: Q200
R15 R42 = CMP-0022680-4: RES, 1.00 k, 1%, 0.1 W, 0603; Manufacturer: Panasonic; Power_W: 100mW; TempCo: 100 ppm/C; Value_Code: 1k00; U/M: EA; EIA_Code: E96; Res_ohm: 1k; SizeX_mm: 1.6; SizeY_mm: 0.8; SizeZ_mm: 1; SizeArea_mm2: 1.28; CompType: Resistor; VDC_V: 75V; AEC Category: Q200; Value2: 0.1W
R19 = CMP-0016782-3: RES, 20.0, 1%, 0.5 W, AEC-Q200 Grade 0, 1206; Manufacturer: Vishay-Dale; Power_W: 500mW; TempCo: 100 ppm/C; Value_Code: 20R0; Value: 20.0; EIA_Code: E96; SizeX_mm: 3.2; SizeY_mm: 1.6; SizeZ_mm: 1.35; Value2: 0.5W; SizeArea_mm2: 5.12; CompType: Resistor; AEC Qualified: Y; AEC Grade: 0; AEC Category: Q200
R25 = CMP-0022311-4: RES, 2.49, 1%, 0.1 W, AEC-Q200 Grade 0, 0603; Manufacturer: Vishay-Dale; Power_W: 100mW; TempCo: 100 ppm/C; Value_Code: 2R49; EIA_Code: E96; SizeX_mm: 1.6; SizeY_mm: 0.8; SizeZ_mm: 1; Value2: 0.1W; SizeArea_mm2: 1.28; CompType: Resistor; AEC Qualified: Y; VDC_V: 75V; AEC Category: Q200; AEC Grade: 0
R26 = CMP-0022448-4: RES, 49.9, 1%, 0.1 W, AEC-Q200 Grade 0, 0603; Manufacturer: Vishay-Dale; Power_W: 100mW; TempCo: 100 ppm/C; Value_Code: 49R9; EIA_Code: E96; SizeX_mm: 1.6; SizeY_mm: 0.8; SizeZ_mm: 1; Value2: 0.1W; SizeArea_mm2: 1.28; CompType: Resistor; AEC Qualified: Y; VDC_V: 75V; AEC Category: Q200; AEC Grade: 0
R28 = CMP-0017252-2: RES, 0.05, 1%, 0.5 W, 1206; Manufacturer: Bourns; Power_W: 500mW; TempCo: 150 ppm/C; Value_Code: R050; U/M: EA; EIA_Code: E96; SizeX_mm: 3.2; SizeY_mm: 1.6; SizeZ_mm: 1.35; Value2: 0.5W; SizeArea_mm2: 5.12; CompType: Resistor; VDC_V: 0V; AEC Category: Q200
R38 = CMP-0023004-4: RES, 2.00 M, 1%, 0.1 W, 0603; Manufacturer: Yageo; Power_W: 100mW; TempCo: 100 ppm/C; Value_Code: 2M00; EIA_Code: E96; Res_ohm: 2M; SizeX_mm: 1.6; SizeY_mm: 0.8; SizeZ_mm: 1; Value2: 0.1W; SizeArea_mm2: 1.28; CompType: Resistor; AEC Qualified: N; VDC_V: 75V; AEC Category: Q200; ValueDisplayed: 2.00M; SizeAreaWB_mm2: 4.68
R41 = CMP-0022735-5: RES, 100 k, 1%, 0.1 W, 0603; Manufacturer: Yageo; Power_W: 100mW; TempCo: 100 ppm/C; EIA_Code: E96; SizeX_mm: 1.6; SizeY_mm: 0.8; SizeZ_mm: 1; Value2: 0.1W; SizeArea_mm2: 1.28; CompType: Resistor; AEC Qualified: N; VDC_V: 75V; AEC Category: Q200; SizeAreaWB_mm2: 4.68
R43 = CMP-0022692-3: RES, 22.0 k, 1%, 0.1 W, AEC-Q200 Grade 0, 0603; Manufacturer: Panasonic; Power_W: 100mW; TempCo: 100 ppm/C; Value_Code: 22k0; U/M: EA; Res_ohm: 22k; SizeX_mm: 1.6; SizeY_mm: 0.8; SizeZ_mm: 1; Value2: 0.1W; SizeArea_mm2: 1.28; CompType: Resistor; AEC Qualified: Y; VDC_V: 50V; AEC Grade: 0; AEC Category: Q200
R44 = CMP-0023128-4: RES, 470 k, 1%, 0.1 W, 0603; Manufacturer: Yageo; Power_W: 100mW; TempCo: 100 ppm/C; SizeX_mm: 1.6; SizeY_mm: 0.8; SizeZ_mm: 1; Value2: 0.1W; SizeArea_mm2: 1.28; CompType: Resistor; AEC Qualified: N; VDC_V: 75V; AEC Category: Q200; SizeAreaWB_mm2: 4.68
S2 = CMP-0002113-1: Switch, Push Button, SMD; Manufacturer: Alps; CurrentRating_mA: 50A; SwitchFunction: Off-Mom; Circuit: SPST-NO; VDC_V: 12V; PositionCount: 1
TP2 TP3 TP5 TP6 VIN = CMP-0055137-1: Test Point, Miniature, Red, TH; Manufacturer: Keystone; CNHeader: FALSE; Green_Lifecycle: Active; Green_REACh: Passed; ContactFinish: Silver; CT: TRUE
U1 = CMP-0076712-5: High Current, High Efficiency Single Inductor Buck-Boost Converter, DLA0010A (VSON-HR-10); Alternate Manufacturer: Texas Instruments; Alternate PartNumber: TPS63802DLAT; SizeAreaWB_mm2: 12.0; SizeY_mm: 3.0; AEC Category: Q200; SizeArea_mm2: 6.0; CompType: IC; AEC Qualified: N; SizeX_mm: 2.0; SizeZ_mm: 1.0
U2 = CMP-0013459-3: 12V eFuse with Over Voltage Protection, DSG0008A (WSON-8); Alternate PartNumber: TPS259571DSGT; Manufacturer: Texas Instruments; SizeZ_mm: 0.8; SizeX_mm: 2; SizeArea_mm2: 4; CompType: IC; U/M: EA; SizeAreaWB_mm2: 9
U3 U8 = CMP-0040903-1: 17 uA, MicroPower, Precision, Zero Drift CMOS Operational Amplifier, 1.8 to 5.5 V, -40 to 125 degC, 5-pin SOT23 (DBV5), Green (RoHS & no Sb/Br); Manufacturer: Texas Instruments; Sub Family: Low Offset Voltage Amplifier (<=500uV), Low Power Amp (<=500uA), Low Supply Voltage Amplifier (<=2.7V), Precision Amplifier, Zero Drift Precision Amplifier; Offset Drift(Typ)(uV/C): 0.02; Vio (25C)(Max)(mV): 0.01; Iq per channel(Max)(mA): 0.025; Slew Rate(Typ)(V/us): 0.16; CMRR(Min)(dB): 106; Total Supply Voltage(Min)(+5V is 5, +/-5V is 10): 1.8; Number of Channels: 1; IIB(Max)(pA): 200; Total Supply Voltage(Max)(+5V is 5, +/-5V is 10): 5.5
U4 U5 = CMP-0041001-1: 50 MHz, Low-Noise, Single-Supply Rail-to-Rail Operational Amplifier, 2.2 to 5.5 V, -40 to 125 degC, 5-pin SOT23 (DBV5), Green (RoHS & no Sb/Br); Manufacturer: Texas Instruments; Sub Family: High Speed Amplifier (>=50MHz), Low Input Bias Current Amp (<=10pA), Low Noise Amp (<=10nV/rtHz), Low Offset Voltage Amplifier (<=500uV), Low Supply Voltage Amplifier (<=2.7V); Vio (25C)(Max)(mV): 0.2; CMRR(Min)(dB): 100; Total Supply Voltage(Max)(+5V is 5, +/-5V is 10): 5.5; Total Supply Voltage(Min)(+5V is 5, +/-5V is 10): 2.2; Iq per channel(Max)(mA): 5; IIB(Max)(pA): 10; Offset Drift(Typ)(uV/C): 1; Slew Rate(Typ)(V/us): 25
U6 = CMP-0086369-1: 5-V low-leakage-current, 2:1 1-channel precision multiplexer, DCK0006A (SOT-SC70-6); Manufacturer: Texas Instruments; SizeZ_mm: 1.1; Rating: Catalog; AEC Category: Q200; SizeY_mm: 2; SizeX_mm: 2.1; AEC Qualified: N; SizeArea_mm2: 4.2; CompType: IC; SizeAreaWB_mm2: 9.3
U7 = CMP-0085889-1: Small-Size Micropower Low-Voltage Comparator, DCK0005A (SOT-SC70-5); Manufacturer: Texas Instruments; Alternate PartNumber: TLV7021DCKT; SizeX_mm: 2.1; AEC Qualified: N; SizeZ_mm: 1.1; SizeY_mm: 2; AEC Category: Q200; Rating: Catalog; SizeAreaWB_mm2: 9.3; CompType: IC; SizeArea_mm2: 4.2

## Sheet TIDA-010043_EVM_Hardware.SchDoc: Hardware
size 431 x 279 mm; Date: Not shown in title block; ApprovedBy: Not shown in title block; CheckedBy: Not shown in title block; Author: Not shown in title block; CompanyName: Not shown in title block; DrawnBy: Sanjay Pithadia; Engineer: Sanjay Pithadia; Organization: Not shown in title block; Address1: Not shown in title block; Address2: Not shown in title block; Address3: Not shown in title block; Address4: Not shown in title block; DocumentNumber: 1; Revision: Use project parameter SCH_Rev; SheetNumber: 3; SheetTotal: 3; PageSetup: Record=PageOptions¦CenterHorizontal=True¦CenterVertical=True¦PrintScale=1.00¦XCorrection=1.00¦YCorrection=1.00¦PrintKind=0¦BorderSize=5000000¦LeftOffset=0¦BottomOffset=0¦Orientation=2¦PaperLength=1000¦PaperWidth=1000¦Scale=100¦PaperSource=15¦PrintQuality=600¦MediaType=1¦DitherType=10¦PaperKind=Letter¦PrintScaleMode=1
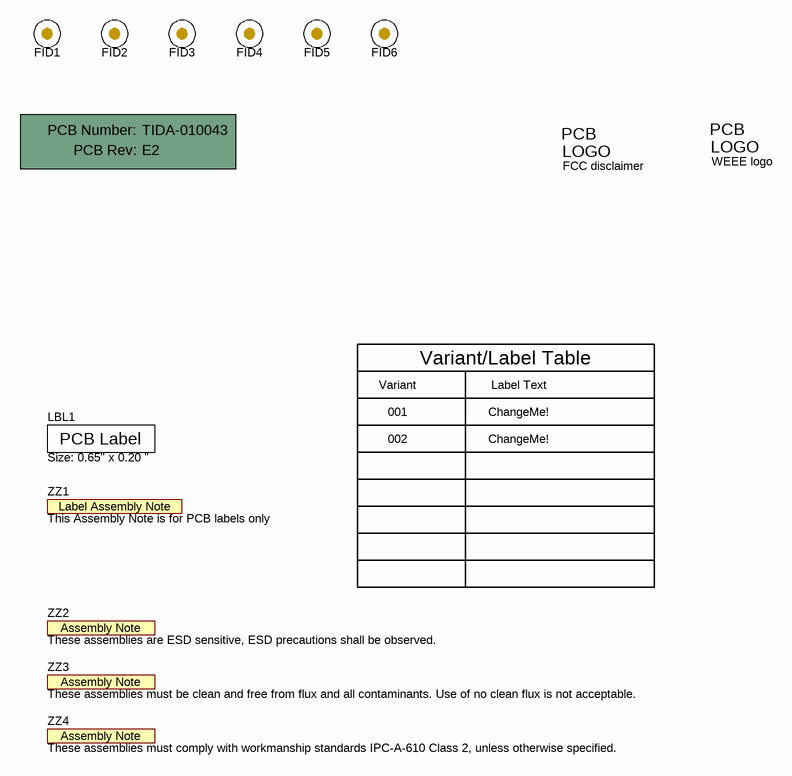
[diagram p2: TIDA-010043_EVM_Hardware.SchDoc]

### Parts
!PCB  Printed Circuit Board  (value not drawn)  (mechanical)
FID1  Fiducial  [Fiducial10-20]  (value not drawn)
FID2  Fiducial  [Fiducial10-20]  (value not drawn)
FID3  Fiducial  [Fiducial10-20]  (value not drawn)
FID4  Fiducial  [Fiducial10-20]  (value not drawn)
FID5  Fiducial  [Fiducial10-20]  (value not drawn)
FID6  Fiducial  [Fiducial10-20]  (value not drawn)
LBL1  Size: 0.65" x 0.20 "  [Label_650x200]
Logo3  FCC disclaimer  [FCC_disclaimer]  (no BOM)
Logo4  WEEE logo  [WEEE_Minimum]  (no BOM)
ZZ1  This Assembly Note is for PCB labels only  [AssemblyNoteLabel]  (no BOM)
ZZ2  These assemblies are ESD sensitive, ESD precautions shall be observed.  [AssemblyNote]  (no BOM)
ZZ3  These assemblies must be clean and free from flux and all contaminants. Use of no clean flux is not acceptable.  [AssemblyNote]  (no BOM)
ZZ4  These assemblies must comply with workmanship standards IPC-A-610 Class 2, unless otherwise specified.  [AssemblyNote]  (no BOM)

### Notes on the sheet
- Variant
- Variant/Label Table
- Label Text
- 001
- 002
- ChangeMe!

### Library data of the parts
!PCB = PCB: Manufacturer: Any; PartNumber: TIDA-010043; SymbolCreator: a0412235
FID1-FID6 = Fiducial: Fiducial mark.  There is nothing to buy or mount.; SymbolCreator: codlsc
LBL1 = THT-14-423-10: Thermal Transfer Printable Labels, 0.650" W x 0.200" H - 10,000 per roll; Manufacturer: Brady; SymbolCreator: a0412235; CompType: Label
Logo3 = FCC_disclaimer: SymbolCreator: codlsc
Logo4 = CMP-0074769-1
ZZ1 = AssemblyNoteLabel: SymbolCreator: a0412235
ZZ2-ZZ4 = AssemblyNote: SymbolCreator: codlsc

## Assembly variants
001: not fitted D3 FID1 FID2 FID3 J5 R27 R47 R48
